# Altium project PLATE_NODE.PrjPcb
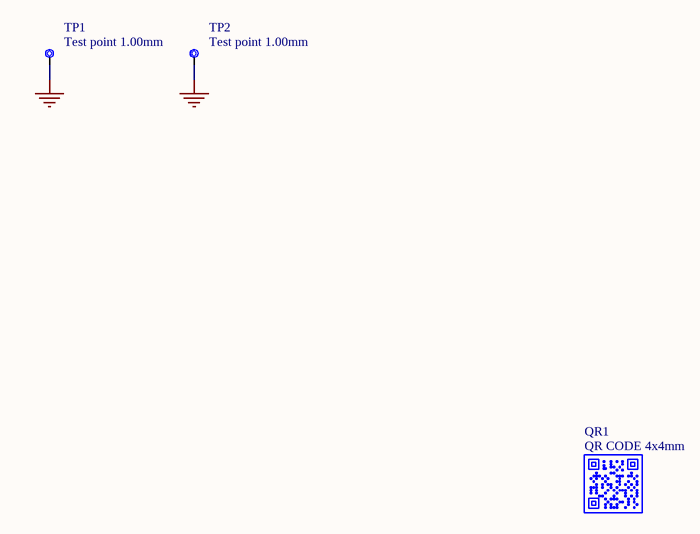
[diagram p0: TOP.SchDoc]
ASSEMBLY_BGA: _; ASSEMBLY_PRESSFIT: _; ASSEMBLY_SMD: -; ASSEMBLY_THT: _; BOARD_CODENAME: PLATE_NODE; BOARD_INFO_AUTHOR: Daniela Catanzaro; BOARD_INFO_AUTHOR_REV: Daniela Catanzaro; BOARD_INFO_Er: _; BOARD_INFO_FLEX: _; BOARD_INFO_FR4: X; BOARD_INFO_FR4_HTG: _; BOARD_INFO_IPC1: _; BOARD_INFO_IPC2: X; BOARD_INFO_IPC3: _; BOARD_INFO_IPC_NA: -; BOARD_INFO_NUMBER_OF_LAYERS: 2; BOARD_INFO_PCB_SIZE: 140mmx140mm; BOARD_INFO_POLYMIDE: _; BOARD_INFO_RIGID: X; BOARD_INFO_RIGID/FLEX: _; BOARD_INFO_TBD: _; BOARD_INFO_THICKNESS: 1.6mm; DRILLS_BLIND: _; DRILLS_BURIED: _; DRILLS_COPPER_FILLING: _; DRILLS_FULL: X; DRILLS_LASER: _; DRILLS_PRESSFIT: _; DRILLS_RESIN_FILLING: _; DRILLS_SLOT: _; DRILLS_SOLDER_FILLING: X; FINISH_ADJUSTMENTS: _; FINISH_EDGE_PLATING: _; FINISH_ENIG: _; FINISH_HAL: _; FINISH_HAL_LF: X; FINISH_NI/AU: _; FINISH_SILK_BOTTOM: X; FINISH_SILK_COLOR: WHITE; FINISH_SILK_TOP: X; FINISH_SN/PB: _; FINISH_SOLDERMASK_BOTTOM: X; FINISH_SOLDERMASK_COLOR: YELLOW; FINISH_SOLDERMASK_PEELABLE_BOTTOM: _; FINISH_SOLDERMASK_PEELABLE_COLOR: _; FINISH_SOLDERMASK_PEELABLE_TOP: _; FINISH_SOLDERMASK_TOP: X; FINISH_TABS: _; FINISH_TBD: _; INSULATION_MIN_INNER: 0.3mm; INSULATION_MIN_OUTER: 0.3mm; PANEL_MILLING: X; PANEL_NOT_REQUESTED: _; PANEL_NUMBER_OF_FIGURES: 4; PANEL_PROVIDED: X; PANEL_REQUESTED: _; PANEL_SCORING: X; PANEL_SIZE: 291mmx298mm; PANEL_TABS: _; SKU: ASX00071; TRACK_MIN_WIDTH_INNER: 0.3mm; TRACK_MIN_WIDTH_OUTER: 0.3mm; Version: V0.2; VIA_1: _; VIA_1_HOLE_MM: _; VIA_1_PAD_MM: _; VIA_2: _; VIA_2_HOLE_MM: _; VIA_2_PAD_MM: _; VIA_3: _; VIA_3_HOLE_MM: _; VIA_3_PAD_MM: _; VIA_4: _; VIA_4_HOLE_MM: _; VIA_4_PAD_MM: _; VIA_5: _; VIA_5_HOLE_MM: _; VIA_5_PAD_MM: _; VIA_THROUGH: -; VIA_THROUGH_HOLE_MM: -; VIA_THROUGH_PAD_MM: -
1 sheet, 3 parts. Net scope: hierarchical (ports join the sheet entries above them; power ports are global).
Board file: PCB.PcbDoc

## Sheet TOP.SchDoc: TOP
size A4; Revision: V0.2; SheetNumber: 1; SheetTotal: 1

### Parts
QR1  QR CODE 4x4mm  [QR CODE 4x4mm]  (no BOM)
TP1  Test point 1.00mm  [TP-1.00MM]  (no BOM)
TP2  Test point 1.00mm  [TP-1.00MM]  (no BOM)

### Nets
GND: TP1.X TP2.X

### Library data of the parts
QR1 = QR-0001-A.2: QR CODE 4x4mm on layer 34 (This is not a component); Code Arduino: QRCODE_4x4mm
TP1 TP2 = UT0013-A.6: Manufacturer: This is not a component

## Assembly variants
ASX00071: all parts fitted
